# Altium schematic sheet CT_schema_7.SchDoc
size 391 x 238 mm
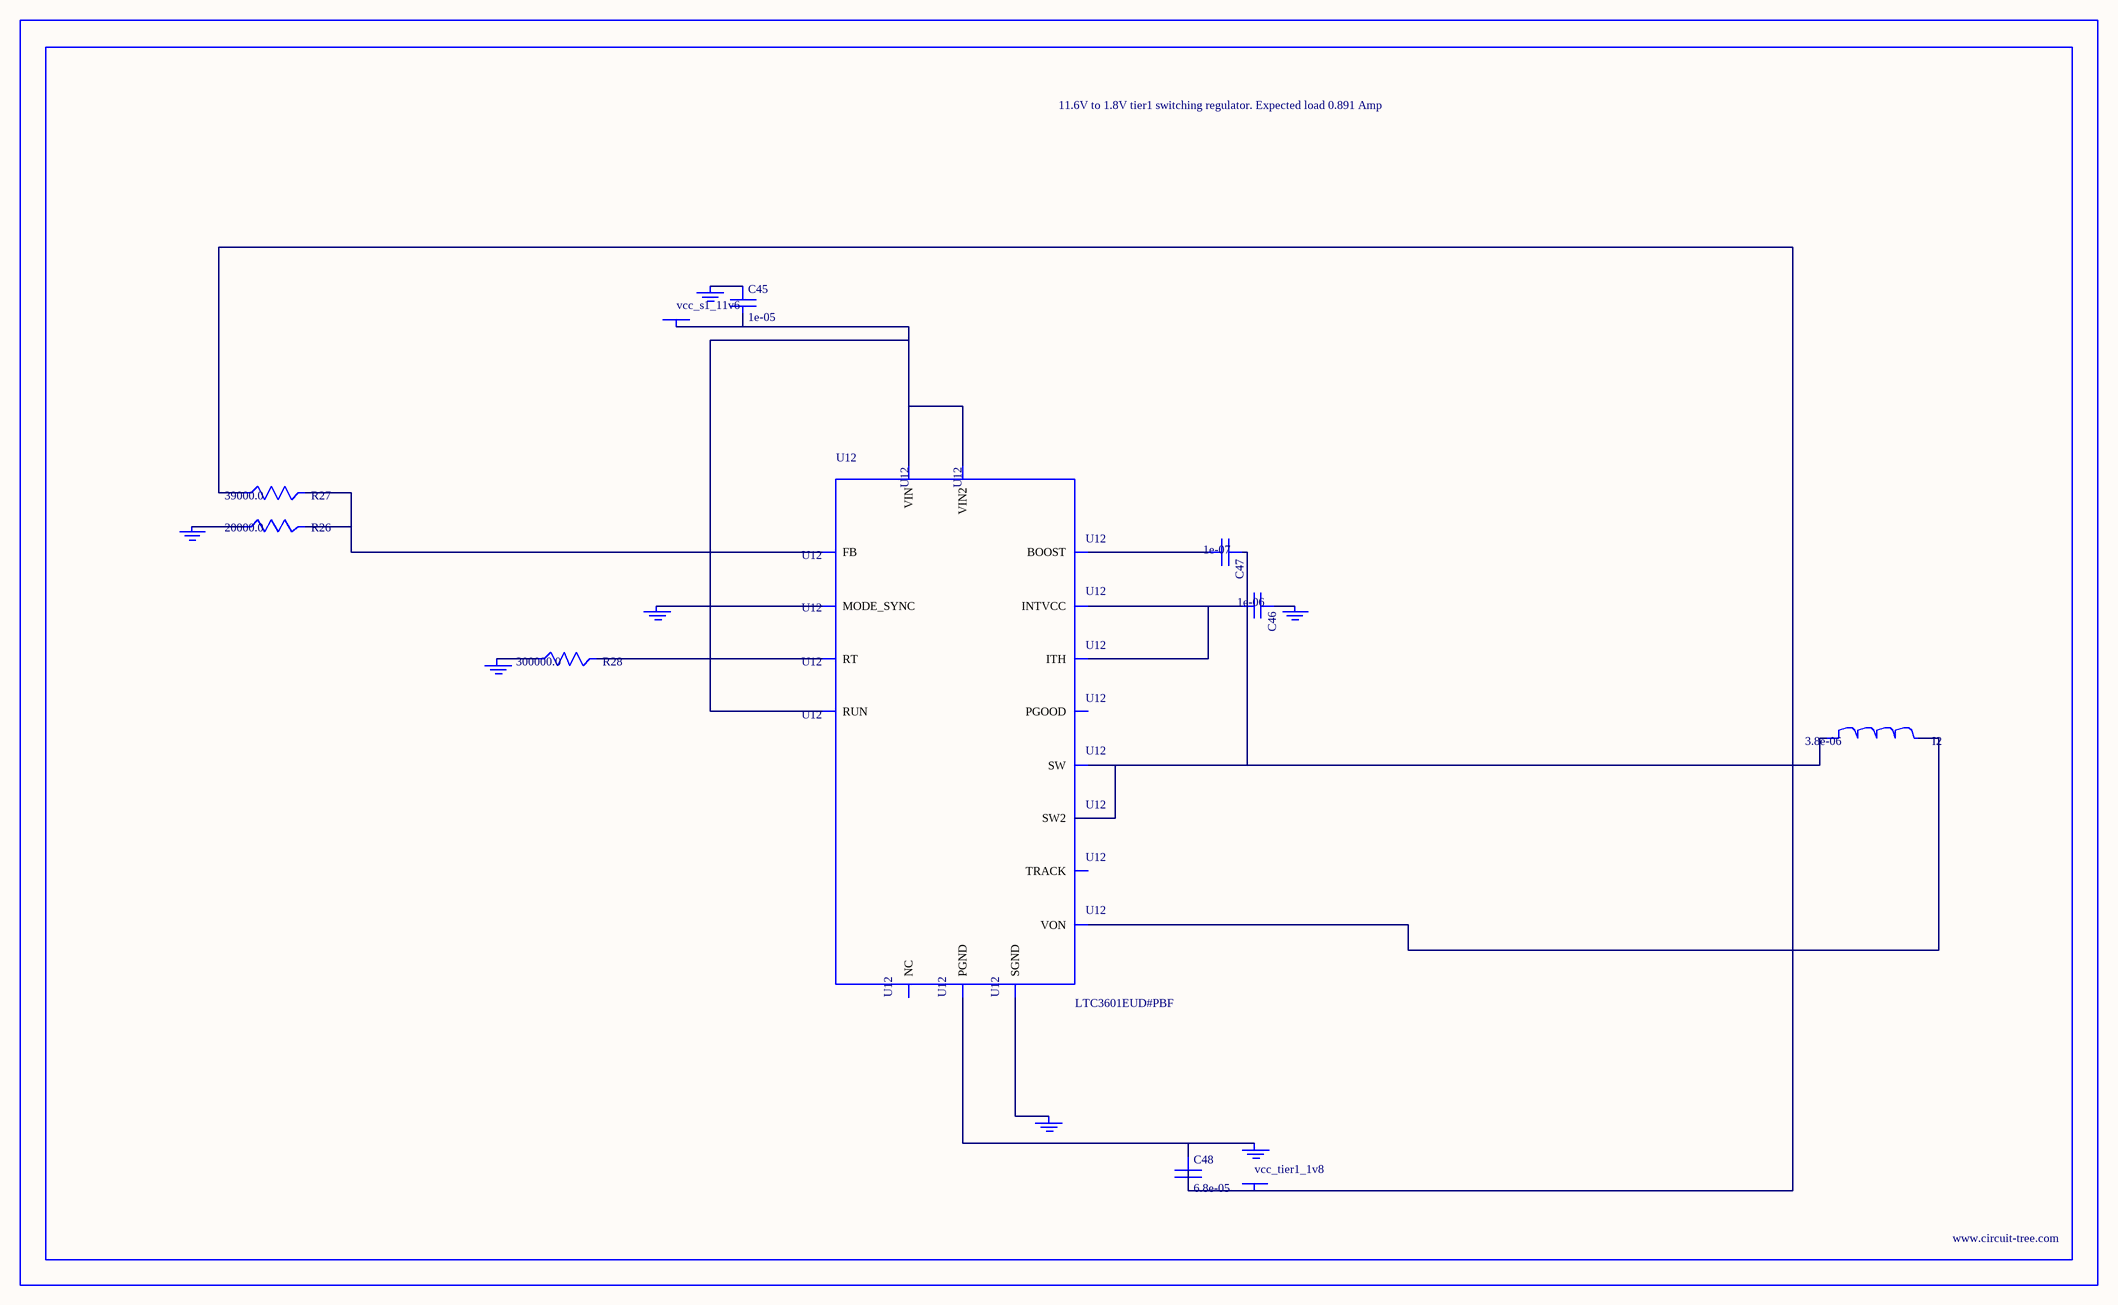
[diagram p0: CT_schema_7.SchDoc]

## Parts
BORDER6  (no value)
C45  1e-05  [C0805]
C46  1e-06  [C0603]
C47  1e-07  [C0402]
C48  6.8e-05  [2220]
GND_INSTANCE_6_0  (no value)
GND_INSTANCE_6_1  (no value)
GND_INSTANCE_6_2  (no value)
GND_INSTANCE_6_3  (no value)
GND_INSTANCE_6_4  (no value)
GND_INSTANCE_6_5  (no value)
GND_INSTANCE_6_6  (no value)
I2  3.8e-06  [DR1040]
POWER_INSTANCE_6_0  vcc_s1_11v6
POWER_INSTANCE_6_1  vcc_tier1_1v8
R26  20000.0  [R0603]
R27  39000.0  [R0603]
R28  300000.0  [R0603]
U12  LTC3601EUD#PBF  [QFN-16_EP]

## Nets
NetC45_1: C45.1 GND_INSTANCE_6_5.0(GND)
NetC45_2: C45.2 POWER_INSTANCE_6_0.0(PWR) U12.14(RUN) U12.15(VIN) U12.16(VIN2)
NetC46_1: C46.1 GND_INSTANCE_6_1.0(GND)
NetC46_2: C46.2 U12.7(INTVCC) U12.12(ITH)
NetC47_1: C47.1 I2.1 U12.3(SW) U12.4(SW2)
NetC47_2: C47.2 U12.6(BOOST)
NetC48_1: C48.1 GND_INSTANCE_6_6.0(GND) U12.17(PGND)
NetC48_2: C48.2 I2.2 POWER_INSTANCE_6_1.0(PWR) R27.1 U12.8(VON)
NetGND_INSTANCE_6_0_0: GND_INSTANCE_6_0.0(GND) U12.1(MODE_SYNC)
NetGND_INSTANCE_6_2_0: GND_INSTANCE_6_2.0(GND) U12.9(SGND)
NetGND_INSTANCE_6_3_0: GND_INSTANCE_6_3.0(GND) R28.1
NetGND_INSTANCE_6_4_0: GND_INSTANCE_6_4.0(GND) R26.1
NetR26_2: R26.2 R27.2 U12.11(FB)
NetR28_2: R28.2 U12.10(RT)

Not connected (* = marked no-connect by the designer): U12 2(PGOOD) 5(NC) 13(TRACK)

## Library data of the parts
BORDER6 = BORDER_PAGE6
C45 = C0805C106K8RACTU
C46 = C0603C105K3RACTU
C47 = C0402C104K3RACTU
C48 = C5750X5R1A686M
GND_INSTANCE_6_0-GND_INSTANCE_6_6 = GND
I2 = DR1040-3R8-R
POWER_INSTANCE_6_0 POWER_INSTANCE_6_1 = PWR
R26 = RC0603JR-0720KL
R27 = RC0603JR-0739KL
R28 = RC0603JR-07300KL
